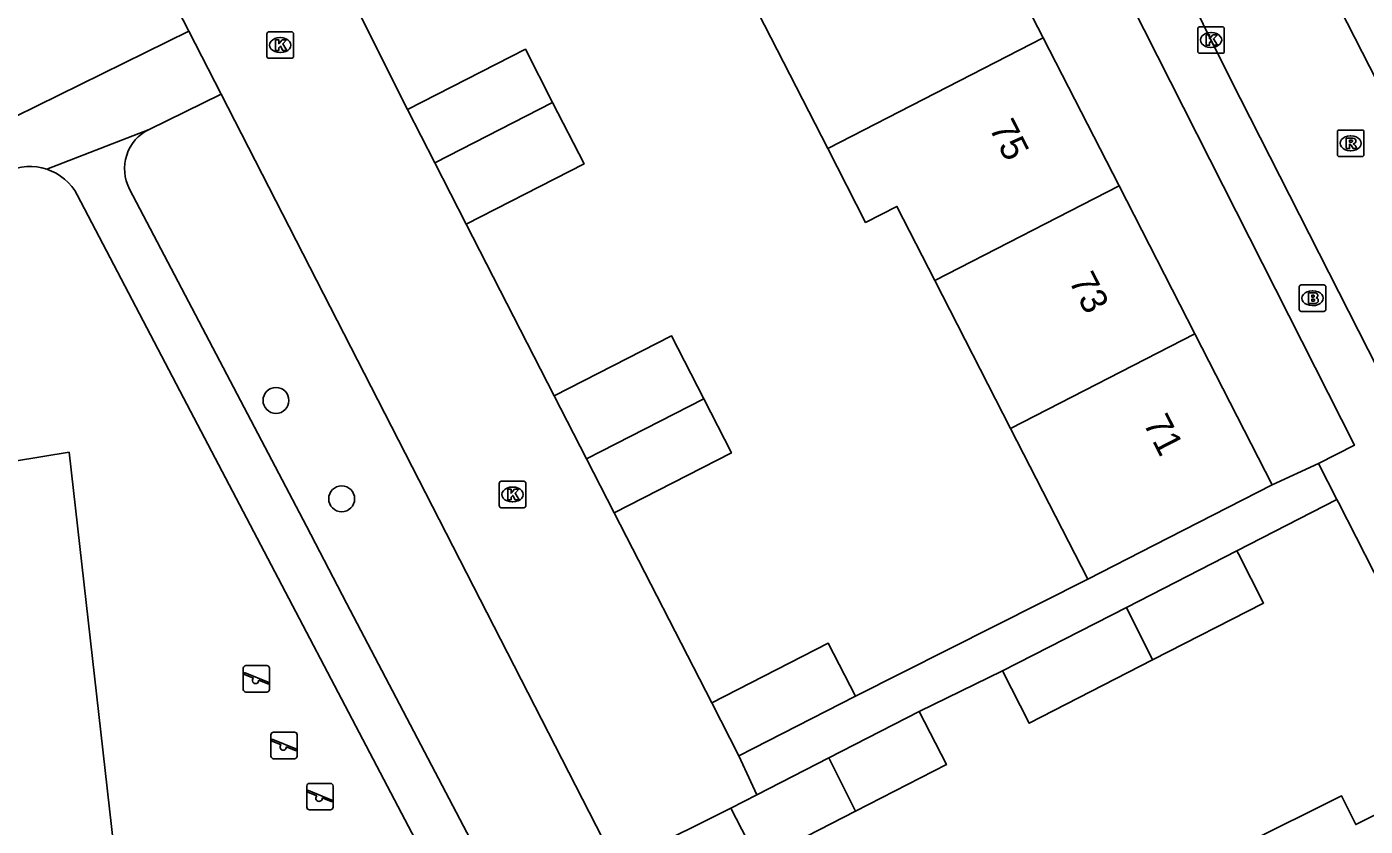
# Model space of a CAD drawing. Extents: x 158461 to 159795, y 387220 to 388672.
# Drawn here: x 159007 to 159057.5, y 387958.2 to 387988.4 of the extents above; entities that cross this region are included whole.
import ezdxf

# ---------------------------------------------------------------- set-up
doc = ezdxf.new("R2010")
doc.units = 0
for name, color, linetype in [('IMGEO_Boom', 7, 'Continuous'), ('IMGEO_Brandkraan', 7, 'Continuous'), ('IMGEO_Groenvoorziening', 7, 'Continuous'), ('IMGEO_Kolk', 7, 'Continuous'), ('IMGEO_Pand', 7, 'Continuous'), ('IMGEO_Pand_nummerreeks', 7, 'Continuous'), ('IMGEO_Rijbaan_lokaal_open', 7, 'Continuous'), ('IMGEO_Rioolput', 7, 'Continuous'), ('IMGEO_Speelvoorziening', 7, 'Continuous'), ('IMGEO_Voetpad_halfverhard', 7, 'Continuous'), ('IMGEO_Voetpad_open', 7, 'Continuous')]:
    doc.layers.add(name, color=color, linetype=linetype)

msp = doc.modelspace()

# ---------------------------------------------------------------- linework, layer by layer
at = {"layer": 'IMGEO_Boom'}
for centre in [(159016.378, 387974.257), (159018.856, 387970.545)]:
    msp.add_circle(centre, 0.489, dxfattribs=at)
at = {"layer": 'IMGEO_Brandkraan'}
for p, q in [((159054.978, 387977.688), (159054.978, 387978.54)), ((159055.053, 387978.614), (159055.905, 387978.614)), ((159055.466, 387978.394), (159055.491, 387978.394)), ((159055.979, 387978.54), (159055.979, 387977.688)), ((159055.489, 387977.834), (159055.464, 387977.834)), ((159055.905, 387977.614), (159055.053, 387977.614))]:
    msp.add_line(p, q, dxfattribs=at)
for points in [[(159054.978, 387977.688), (159054.978, 387978.54)], [(159055.053, 387978.614), (159055.905, 387978.614)], [(159055.326, 387978.314), (159055.326, 387977.914), (159055.539, 387977.914)], [(159055.557, 387978.314), (159055.326, 387978.314)], [(159055.505, 387978.233), (159055.451, 387978.233), (159055.451, 387978.157)], [(159055.979, 387978.54), (159055.979, 387977.688)], [(159055.451, 387978.157), (159055.504, 387978.157)], [(159055.513, 387978.081), (159055.451, 387978.081), (159055.451, 387978)], [(159055.451, 387978), (159055.513, 387978)], [(159055.905, 387977.614), (159055.053, 387977.614)]]:
    msp.add_lwpolyline(points, dxfattribs=at)
for centre, radius, start, end in [((159055.055, 387978.538), 0.0765, 91.552, 178.448), ((159055.055, 387978.538), 0.0765, 91.552, 178.448), ((159055.506, 387978.195), 0.0379, 267.8285, 90.9355), ((159055.561, 387978.169), 0.145, 59.4692, 91.5367), ((159055.586, 387978.216), 0.0922, 285.5137, 58.1501), ((159055.903, 387978.538), 0.0765, 1.552, 88.448), ((159055.903, 387978.538), 0.0765, 1.552, 88.448), ((159055.055, 387977.69), 0.0765, 181.552, 268.448), ((159055.055, 387977.69), 0.0765, 181.552, 268.448), ((159055.514, 387978.04), 0.0404, 269.8759, 90.5077), ((159055.545, 387978.165), 0.251, 268.6676, 293.5347), ((159055.591, 387978.024), 0.105, 301.3115, 78.989), ((159055.903, 387977.69), 0.0765, 271.552, 358.448), ((159055.903, 387977.69), 0.0765, 271.552, 358.448)]:
    msp.add_arc(centre, radius, start, end, dxfattribs=at)
for centre, major_axis, ratio, start_param, end_param in [((159055.465, 387978.114), (-0.387, 0.002), 0.722429, 4.712389, 7.853982), ((159055.49, 387978.114), (-0.39, 0.002), 0.717154, 1.570796, 4.712389)]:
    msp.add_ellipse(centre, major_axis=major_axis, ratio=ratio, start_param=start_param, end_param=end_param, dxfattribs=at)
at = {"layer": 'IMGEO_Groenvoorziening'}
msp.add_lwpolyline([(159008.574, 387972.298), (159012.648, 387936.275), (159004.786, 387936.227), (159000.315, 387936.046), (158997.187, 387970.431), (159008.574, 387972.298)], dxfattribs=at)
at = {"layer": 'IMGEO_Kolk'}
for p, q in [((159051.148, 387987.427), (159051.148, 387988.279)), ((159051.223, 387988.353), (159052.075, 387988.353)), ((159052.149, 387988.279), (159052.149, 387987.427)), ((159016.039, 387987.237), (159016.039, 387988.089)), ((159016.114, 387988.163), (159016.966, 387988.163)), ((159016.527, 387987.943), (159016.552, 387987.943)), ((159017.04, 387988.089), (159017.04, 387987.237)), ((159051.636, 387988.133), (159051.661, 387988.133)), ((159016.55, 387987.383), (159016.525, 387987.383)), ((159052.075, 387987.353), (159051.223, 387987.353)), ((159051.659, 387987.573), (159051.634, 387987.573)), ((159016.966, 387987.163), (159016.114, 387987.163)), ((159024.803, 387970.282), (159024.803, 387971.134)), ((159024.878, 387971.208), (159025.73, 387971.208)), ((159025.804, 387971.134), (159025.804, 387970.282)), ((159025.291, 387970.988), (159025.316, 387970.988)), ((159025.73, 387970.208), (159024.878, 387970.208)), ((159025.314, 387970.428), (159025.289, 387970.428))]:
    msp.add_line(p, q, dxfattribs=at)
for points in [[(159051.148, 387987.427), (159051.148, 387988.279)], [(159051.223, 387988.353), (159052.075, 387988.353)], [(159052.149, 387988.279), (159052.149, 387987.427)], [(159016.039, 387987.237), (159016.039, 387988.089)], [(159016.114, 387988.163), (159016.966, 387988.163)], [(159016.36, 387987.863), (159016.483, 387987.863), (159016.483, 387987.712), (159016.613, 387987.863), (159016.777, 387987.863), (159016.631, 387987.712), (159016.784, 387987.463), (159016.632, 387987.463), (159016.547, 387987.627), (159016.483, 387987.56), (159016.483, 387987.463), (159016.36, 387987.463), (159016.36, 387987.863)], [(159017.04, 387988.089), (159017.04, 387987.237)], [(159051.469, 387988.053), (159051.592, 387988.053), (159051.592, 387987.902), (159051.722, 387988.053), (159051.886, 387988.053), (159051.74, 387987.902), (159051.893, 387987.653), (159051.741, 387987.653), (159051.656, 387987.817), (159051.592, 387987.75), (159051.592, 387987.653), (159051.469, 387987.653), (159051.469, 387988.053)], [(159052.075, 387987.353), (159051.223, 387987.353)], [(159016.966, 387987.163), (159016.114, 387987.163)], [(159024.803, 387970.282), (159024.803, 387971.134)], [(159024.878, 387971.208), (159025.73, 387971.208)], [(159025.804, 387971.134), (159025.804, 387970.282)], [(159025.124, 387970.908), (159025.247, 387970.908), (159025.247, 387970.757), (159025.377, 387970.908), (159025.541, 387970.908), (159025.395, 387970.757), (159025.548, 387970.508), (159025.396, 387970.508), (159025.311, 387970.672), (159025.247, 387970.605), (159025.247, 387970.508), (159025.124, 387970.508), (159025.124, 387970.908)], [(159025.73, 387970.208), (159024.878, 387970.208)]]:
    msp.add_lwpolyline(points, dxfattribs=at)
for centre, start, end in [((159051.225, 387988.277), 91.552, 178.448), ((159051.225, 387988.277), 91.552, 178.448), ((159052.073, 387988.277), 1.552, 88.448), ((159052.073, 387988.277), 1.552, 88.448), ((159016.116, 387988.087), 91.552, 178.448), ((159016.116, 387988.087), 91.552, 178.448), ((159016.964, 387988.087), 1.552, 88.448), ((159016.964, 387988.087), 1.552, 88.448), ((159051.225, 387987.429), 181.552, 268.448), ((159051.225, 387987.429), 181.552, 268.448), ((159052.073, 387987.429), 271.552, 358.448), ((159052.073, 387987.429), 271.552, 358.448), ((159016.116, 387987.239), 181.552, 268.448), ((159016.116, 387987.239), 181.552, 268.448), ((159016.964, 387987.239), 271.552, 358.448), ((159016.964, 387987.239), 271.552, 358.448), ((159024.88, 387971.132), 91.552, 178.448), ((159024.88, 387971.132), 91.552, 178.448), ((159025.728, 387971.132), 1.552, 88.448), ((159025.728, 387971.132), 1.552, 88.448), ((159024.88, 387970.284), 181.552, 268.448), ((159024.88, 387970.284), 181.552, 268.448), ((159025.728, 387970.284), 271.552, 358.448), ((159025.728, 387970.284), 271.552, 358.448)]:
    msp.add_arc(centre, 0.0765, start, end, dxfattribs=at)
for centre, major_axis, ratio, start_param, end_param in [((159016.526, 387987.663), (-0.387, 0.002), 0.722429, 4.712389, 7.853982), ((159016.551, 387987.663), (-0.39, 0.002), 0.717154, 1.570796, 4.712389), ((159051.635, 387987.853), (-0.387, 0.002), 0.722429, 4.712389, 7.853982), ((159051.66, 387987.853), (-0.39, 0.002), 0.717154, 1.570796, 4.712389), ((159025.29, 387970.708), (-0.387, 0.002), 0.722429, 4.712389, 7.853982), ((159025.315, 387970.708), (-0.39, 0.002), 0.717154, 1.570796, 4.712389)]:
    msp.add_ellipse(centre, major_axis=major_axis, ratio=ratio, start_param=start_param, end_param=end_param, dxfattribs=at)
at = {"layer": 'IMGEO_Pand'}
for points in [[(159045.315, 387987.932), (159044.134, 387990.235), (159043.088, 387989.699), (159041.407, 387992.978)], [(159034.326, 387989.348), (159037.188, 387983.764)], [(159037.188, 387983.764), (159045.315, 387987.932)], [(159048.177, 387982.349), (159045.315, 387987.932)], [(159021.338, 387985.227), (159025.786, 387987.506), (159026.815, 387985.498)], [(159022.368, 387983.218), (159026.815, 387985.498)], [(159026.815, 387985.498), (159028.002, 387983.182), (159023.554, 387980.903)], [(159022.368, 387983.218), (159021.338, 387985.227)], [(159037.188, 387983.764), (159038.619, 387980.972), (159039.798, 387981.577), (159041.229, 387978.786)], [(159023.554, 387980.903), (159022.368, 387983.218)], [(159048.177, 387982.349), (159041.229, 387978.786)], [(159051.038, 387976.766), (159048.177, 387982.349)], [(159041.229, 387978.786), (159044.09, 387973.203)], [(159026.877, 387974.43), (159031.293, 387976.694), (159032.512, 387974.316)], [(159044.09, 387973.203), (159051.038, 387976.766)], [(159053.955, 387971.076), (159051.038, 387976.766)], [(159028.096, 387972.051), (159026.877, 387974.43)], [(159032.512, 387974.316), (159028.096, 387972.051)], [(159032.512, 387974.316), (159033.556, 387972.278), (159029.14, 387970.014)], [(159044.09, 387973.203), (159047.006, 387967.514)], [(159029.14, 387970.014), (159028.096, 387972.051)], [(159053.955, 387971.076), (159049.506, 387968.796), (159047.006, 387967.514)], [(159048.454, 387966.447), (159052.621, 387968.584)], [(159052.621, 387968.584), (159052.681, 387968.467), (159053.632, 387966.611), (159049.444, 387964.464)], [(159043.781, 387964.052), (159048.454, 387966.447)], [(159049.444, 387964.464), (159048.454, 387966.447)], [(159032.813, 387962.842), (159037.21, 387965.096), (159038.235, 387963.096)], [(159049.444, 387964.464), (159044.792, 387962.079), (159043.781, 387964.052)], [(159038.235, 387963.096), (159033.838, 387960.842)], [(159033.838, 387960.842), (159032.813, 387962.842)], [(159037.227, 387960.766), (159040.639, 387962.515)], [(159040.639, 387962.515), (159041.664, 387960.515), (159038.232, 387958.756)], [(159034.518, 387959.378), (159037.227, 387960.766)], [(159038.232, 387958.756), (159037.227, 387960.766)], [(159033.538, 387958.876), (159034.518, 387959.378)], [(159057, 387949.342), (159058.849, 387950.265), (159059.409, 387949.145), (159063.294, 387951.086), (159059.194, 387959.296), (159057.109, 387958.255), (159056.567, 387959.341), (159052.915, 387957.518)], [(159038.232, 387958.756), (159034.563, 387956.875), (159033.538, 387958.876)]]:
    msp.add_lwpolyline(points, dxfattribs=at)
at = {"layer": 'IMGEO_Rijbaan_lokaal_open'}
for points in [[(159043.688, 388004.531), (159045.063, 388001.423), (159045.747, 388000), (159049.307, 387992.587), (159052.377, 387986.378), (159057.958, 387975.428), (159061.964, 387967.43)], [(159017.723, 387992.48), (159021.338, 387985.227)], [(159062.264, 387977.834), (159062.104, 387978.096), (159055.389, 387991.241), (159055.2, 387991.702)], [(159013.094, 387988.193), (159011.827, 387990.67)], [(159014.315, 387985.808), (159013.094, 387988.193)], [(159030.077, 387957.144), (159029.22, 387956.715), (159014.315, 387985.808)], [(159023.554, 387980.903), (159026.877, 387974.43)], [(159029.14, 387970.014), (159032.813, 387962.842)], [(159033.838, 387960.842), (159034.518, 387959.378)], [(159033.538, 387958.876), (159030.077, 387957.144)]]:
    msp.add_lwpolyline(points, dxfattribs=at)
at = {"layer": 'IMGEO_Rioolput'}
for p, q in [((159056.414, 387983.53), (159056.414, 387984.382)), ((159056.489, 387984.456), (159057.341, 387984.456)), ((159056.902, 387984.236), (159056.927, 387984.236)), ((159057.415, 387984.382), (159057.415, 387983.53)), ((159057.341, 387983.456), (159056.489, 387983.456)), ((159056.925, 387983.676), (159056.9, 387983.676))]:
    msp.add_line(p, q, dxfattribs=at)
for points in [[(159056.414, 387983.53), (159056.414, 387984.382)], [(159056.489, 387984.456), (159057.341, 387984.456)], [(159057.415, 387984.382), (159057.415, 387983.53)], [(159057.003, 387984.154), (159056.751, 387984.156), (159056.751, 387983.756)], [(159056.751, 387983.756), (159056.875, 387983.756), (159056.875, 387983.918), (159056.886, 387983.918)], [(159056.929, 387984.075), (159056.875, 387984.075), (159056.875, 387983.994)], [(159056.875, 387983.994), (159056.927, 387983.994)], [(159056.933, 387983.889), (159057.004, 387983.756), (159057.144, 387983.756), (159057.079, 387983.882)], [(159057.341, 387983.456), (159056.489, 387983.456)]]:
    msp.add_lwpolyline(points, dxfattribs=at)
for centre, radius, start, end in [((159056.491, 387984.38), 0.0765, 91.552, 178.448), ((159056.491, 387984.38), 0.0765, 91.552, 178.448), ((159057.339, 387984.38), 0.0765, 1.552, 88.448), ((159057.339, 387984.38), 0.0765, 1.552, 88.448), ((159056.885, 387983.865), 0.0533, 26.0293, 88.6989), ((159056.911, 387984.183), 0.19, 274.7715, 282.9687), ((159056.935, 387983.979), 0.0964, 77.0061, 93.1865), ((159056.949, 387984.036), 0.0378, 276.6634, 79.6772), ((159057.002, 387984.044), 0.109, 350.3612, 89.416), ((159057, 387984.044), 0.112, 277.5842, 350.9817), ((159056.984, 387983.829), 0.108, 29.5134, 73.7905), ((159056.491, 387983.532), 0.0765, 181.552, 268.448), ((159056.491, 387983.532), 0.0765, 181.552, 268.448), ((159057.339, 387983.532), 0.0765, 271.552, 358.448), ((159057.339, 387983.532), 0.0765, 271.552, 358.448)]:
    msp.add_arc(centre, radius, start, end, dxfattribs=at)
for centre, major_axis, ratio, start_param, end_param in [((159056.901, 387983.956), (-0.387, 0.002), 0.722429, 4.712389, 7.853982), ((159056.926, 387983.956), (-0.39, 0.002), 0.717154, 1.570796, 4.712389)]:
    msp.add_ellipse(centre, major_axis=major_axis, ratio=ratio, start_param=start_param, end_param=end_param, dxfattribs=at)
at = {"layer": 'IMGEO_Speelvoorziening'}
for p, q in [((159015.145, 387963.352), (159015.145, 387964.152)), ((159015.145, 387964.152), (159015.145, 387963.352)), ((159015.245, 387964.252), (159016.035, 387964.252)), ((159016.035, 387964.252), (159015.245, 387964.252)), ((159016.135, 387964.152), (159016.135, 387963.352)), ((159016.135, 387963.352), (159016.135, 387964.152)), ((159015.528, 387963.78), (159015.189, 387963.917)), ((159015.214, 387963.977), (159016.09, 387963.624)), ((159016.066, 387963.564), (159015.726, 387963.701)), ((159016.035, 387963.252), (159015.245, 387963.252)), ((159015.245, 387963.252), (159016.035, 387963.252)), ((159016.188, 387960.84), (159016.188, 387961.64)), ((159016.188, 387961.64), (159016.188, 387960.84)), ((159016.288, 387961.74), (159017.078, 387961.74)), ((159017.078, 387961.74), (159016.288, 387961.74)), ((159017.178, 387961.64), (159017.178, 387960.84)), ((159017.178, 387960.84), (159017.178, 387961.64)), ((159016.571, 387961.268), (159016.232, 387961.405)), ((159016.257, 387961.465), (159017.133, 387961.112)), ((159017.109, 387961.052), (159016.769, 387961.189)), ((159017.078, 387960.74), (159016.288, 387960.74)), ((159016.288, 387960.74), (159017.078, 387960.74)), ((159017.541, 387958.909), (159017.541, 387959.709)), ((159017.541, 387959.709), (159017.541, 387958.909)), ((159017.61, 387959.534), (159018.486, 387959.181)), ((159017.641, 387959.809), (159018.431, 387959.809)), ((159018.431, 387959.809), (159017.641, 387959.809)), ((159018.531, 387959.709), (159018.531, 387958.909)), ((159018.531, 387958.909), (159018.531, 387959.709)), ((159017.924, 387959.337), (159017.585, 387959.474)), ((159018.462, 387959.121), (159018.122, 387959.258)), ((159018.431, 387958.809), (159017.641, 387958.809)), ((159017.641, 387958.809), (159018.431, 387958.809))]:
    msp.add_line(p, q, dxfattribs=at)
for centre, radius, start, end in [((159015.245, 387964.152), 0.1, 90, 180), ((159015.245, 387964.152), 0.1, 90, 180), ((159016.035, 387964.152), 0.1, 0, 90), ((159016.035, 387964.152), 0.1, 360, 90), ((159015.202, 387963.947), 0.0327, 68.078, 248.078), ((159015.607, 387963.69), 0.12, 130.9928, 5.1632), ((159016.078, 387963.594), 0.0327, 248.078, 68.078), ((159015.245, 387963.352), 0.1, 180, 270), ((159015.245, 387963.352), 0.1, 180, 270), ((159016.035, 387963.352), 0.1, 270, 0), ((159016.035, 387963.352), 0.1, 270, 0), ((159016.288, 387961.64), 0.1, 90, 180), ((159016.288, 387961.64), 0.1, 90, 180), ((159017.078, 387961.64), 0.1, 0, 90), ((159017.078, 387961.64), 0.1, 360, 90), ((159016.245, 387961.435), 0.0327, 68.078, 248.078), ((159016.65, 387961.178), 0.12, 130.9928, 5.1632), ((159017.121, 387961.082), 0.0327, 248.078, 68.078), ((159016.288, 387960.84), 0.1, 180, 270), ((159016.288, 387960.84), 0.1, 180, 270), ((159017.078, 387960.84), 0.1, 270, 0), ((159017.078, 387960.84), 0.1, 270, 0), ((159017.641, 387959.709), 0.1, 90, 180), ((159017.641, 387959.709), 0.1, 90, 180), ((159017.598, 387959.504), 0.0327, 68.078, 248.078), ((159018.431, 387959.709), 0.1, 0, 90), ((159018.431, 387959.709), 0.1, 360, 90), ((159018.003, 387959.247), 0.12, 130.9928, 5.1632), ((159018.474, 387959.151), 0.0327, 248.078, 68.078), ((159017.641, 387958.909), 0.1, 180, 270), ((159017.641, 387958.909), 0.1, 180, 270), ((159018.431, 387958.909), 0.1, 270, 0), ((159018.431, 387958.909), 0.1, 270, 0)]:
    msp.add_arc(centre, radius, start, end, dxfattribs=at)
at = {"layer": 'IMGEO_Voetpad_halfverhard'}
for points in [[(158982.051, 387972.922), (159000, 387981.752), (159013.094, 387988.193)], [(159011.592, 387984.48), (159014.315, 387985.808)], [(159007.736, 387982.98), (159011.592, 387984.48)], [(159024.788, 387955.653), (159019.042, 387966.612), (159017.524, 387969.508), (159010.854, 387982.231)], [(159023.099, 387954.894), (159012.756, 387974.622), (159008.884, 387982.008)]]:
    msp.add_lwpolyline(points, dxfattribs=at)
for centre, radius, start, end in [((159012.317, 387982.997), 1.651, 116.0431, 207.6229), ((159007.113, 387981.082), 1.998, 71.8235, 116.0328), ((159007.113, 387981.08), 1.999, 27.6477, 71.8438)]:
    msp.add_arc(centre, radius, start, end, dxfattribs=at)
at = {"layer": 'IMGEO_Voetpad_open'}
for points in [[(159030.768, 388024.265), (159043.175, 388000), (159057.059, 387972.566), (159055.7, 387971.878)], [(159055.7, 387971.878), (159053.955, 387971.076)], [(159055.7, 387971.878), (159056.398, 387970.519)], [(159052.621, 387968.584), (159056.398, 387970.519)], [(159056.398, 387970.519), (159056.458, 387970.401), (159057.795, 387967.794), (159062.731, 387958.17), (159064.604, 387954.178), (159066.213, 387950.202), (159067.591, 387946.141), (159063.933, 387944.776)], [(159047.006, 387967.514), (159038.235, 387963.096)], [(159040.639, 387962.515), (159043.781, 387964.052)]]:
    msp.add_lwpolyline(points, dxfattribs=at)

# ---------------------------------------------------------------- texts
at = {"layer": 'IMGEO_Pand_nummerreeks'}
for s, p in [('75', (159043.261, 387984.538)), ('73', (159046.271, 387978.774)), ('71', (159049.074, 387973.407))]:
    msp.add_text(s, height=1, rotation=297.1399, dxfattribs=at).set_placement(p)

doc.saveas('drawing.dxf')
